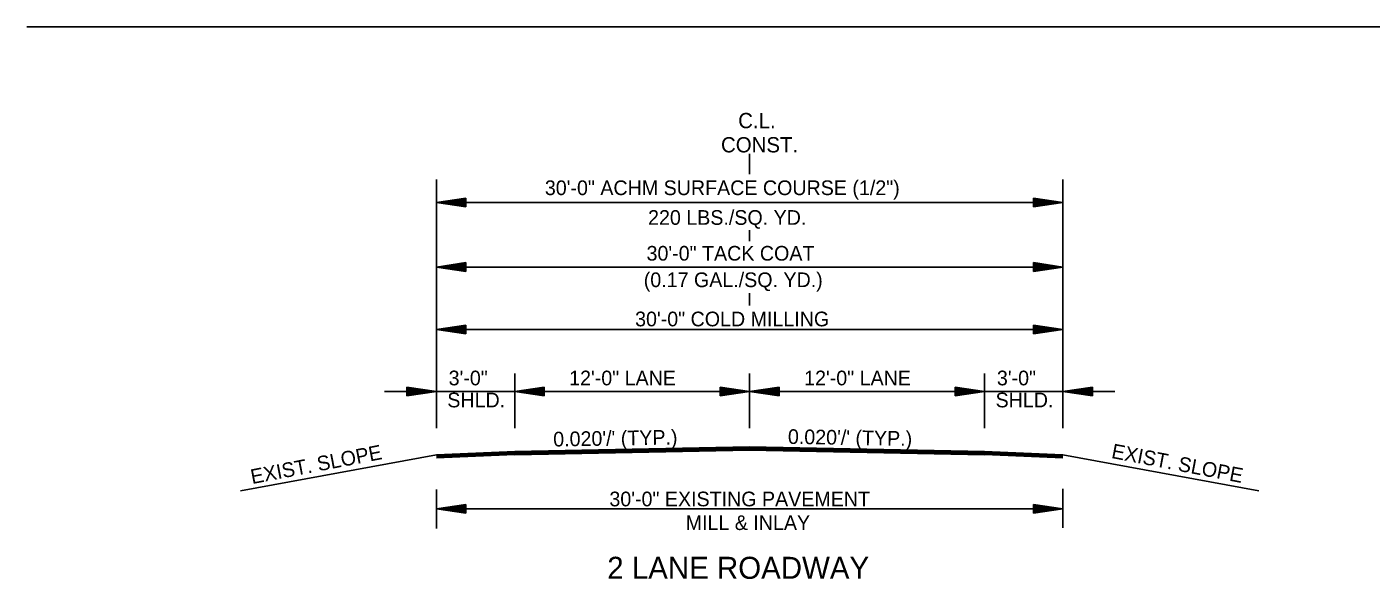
# Model space of a CAD drawing. Extents: x 549600 to 1930787, y -1955432 to 596640.
# Drawn here: x 550993 to 551679, y -1946446 to -1946164 of the extents above; entities that cross this region are included whole.
import ezdxf

# ---------------------------------------------------------------- set-up
doc = ezdxf.new("R2010")
doc.units = 0
doc.layers.add('R_Border', color=7, linetype='Continuous')
doc.layers.add('S_AREA_CALC', color=7, linetype='Continuous')

msp = doc.modelspace()

# ---------------------------------------------------------------- linework, layer by layer
at = {"layer": 'R_Border'}
msp.add_line((550992.91, -1946163.52), (552054.18, -1946163.52), dxfattribs=at)
at = {"layer": 'S_AREA_CALC'}
for p, q in [((551362.02, -1946238.76), (551362.02, -1946228.39)), ((551202.02, -1946368.61), (551202.02, -1946241.57)), ((551522.02, -1946368.61), (551522.02, -1946241.57)), ((551217.02, -1946251), (551202.02, -1946253.25)), ((551217.02, -1946251.37), (551204.52, -1946253.25)), ((551217.02, -1946251.75), (551207.1, -1946253.25)), ((551217.02, -1946252.13), (551209.6, -1946253.25)), ((551217.02, -1946255.5), (551217.02, -1946251)), ((551507.02, -1946251), (551522.02, -1946253.25)), ((551507.02, -1946251), (551507.02, -1946255.5)), ((551507.02, -1946251.37), (551519.51, -1946253.25)), ((551507.02, -1946251.75), (551516.93, -1946253.25)), ((551507.02, -1946252.13), (551514.44, -1946253.25)), ((551202.02, -1946253.25), (551522.02, -1946253.25)), ((551217.02, -1946255.5), (551202.02, -1946253.25)), ((551217.02, -1946255.12), (551204.52, -1946253.25)), ((551217.02, -1946254.74), (551207.1, -1946253.25)), ((551217.02, -1946254.36), (551209.6, -1946253.25)), ((551217.02, -1946252.51), (551212.14, -1946253.25)), ((551217.02, -1946253.97), (551212.14, -1946253.25)), ((551217.02, -1946252.89), (551214.65, -1946253.25)), ((551217.02, -1946253.6), (551214.65, -1946253.25)), ((551507.02, -1946252.52), (551511.89, -1946253.25)), ((551507.02, -1946252.89), (551509.39, -1946253.25)), ((551507.02, -1946255.5), (551522.02, -1946253.25)), ((551507.02, -1946253.98), (551511.89, -1946253.25)), ((551507.02, -1946254.74), (551516.93, -1946253.25)), ((551507.02, -1946255.12), (551519.51, -1946253.25)), ((551507.02, -1946254.36), (551514.44, -1946253.25)), ((551507.02, -1946253.6), (551509.39, -1946253.25)), ((551362.02, -1946272.99), (551362.02, -1946267.45)), ((551217.02, -1946283.96), (551202.02, -1946286.21)), ((551202.02, -1946286.21), (551522.02, -1946286.21)), ((551217.02, -1946288.46), (551202.02, -1946286.21)), ((551217.02, -1946284.34), (551204.52, -1946286.21)), ((551217.02, -1946288.09), (551204.52, -1946286.21)), ((551217.02, -1946284.72), (551207.1, -1946286.21)), ((551217.02, -1946287.7), (551207.1, -1946286.21)), ((551217.02, -1946285.09), (551209.6, -1946286.21)), ((551217.02, -1946287.33), (551209.6, -1946286.21)), ((551217.02, -1946285.48), (551212.14, -1946286.21)), ((551217.02, -1946286.94), (551212.14, -1946286.21)), ((551217.02, -1946285.86), (551214.65, -1946286.21)), ((551217.02, -1946286.56), (551214.65, -1946286.21)), ((551217.02, -1946288.46), (551217.02, -1946283.96)), ((551507.02, -1946283.96), (551522.02, -1946286.21)), ((551507.02, -1946283.96), (551507.02, -1946288.46)), ((551507.02, -1946284.34), (551519.51, -1946286.21)), ((551507.02, -1946284.72), (551516.93, -1946286.21)), ((551507.02, -1946285.09), (551514.44, -1946286.21)), ((551507.02, -1946285.48), (551511.89, -1946286.21)), ((551507.02, -1946285.86), (551509.39, -1946286.21)), ((551507.02, -1946288.46), (551522.02, -1946286.21)), ((551507.02, -1946286.95), (551511.89, -1946286.21)), ((551507.02, -1946287.7), (551516.93, -1946286.21)), ((551507.02, -1946288.09), (551519.51, -1946286.21)), ((551507.02, -1946287.33), (551514.44, -1946286.21)), ((551507.02, -1946286.56), (551509.39, -1946286.21)), ((551362.02, -1946305.95), (551362.02, -1946299.54)), ((551217.02, -1946315.94), (551202.02, -1946318.19)), ((551202.02, -1946318.19), (551522.02, -1946318.19)), ((551217.02, -1946320.44), (551202.02, -1946318.19)), ((551217.02, -1946316.31), (551204.52, -1946318.19)), ((551217.02, -1946320.06), (551204.52, -1946318.19)), ((551217.02, -1946316.69), (551207.1, -1946318.19)), ((551217.02, -1946319.68), (551207.1, -1946318.19)), ((551217.02, -1946317.07), (551209.6, -1946318.19)), ((551217.02, -1946319.3), (551209.6, -1946318.19)), ((551217.02, -1946317.45), (551212.14, -1946318.19)), ((551217.02, -1946318.91), (551212.14, -1946318.19)), ((551217.02, -1946317.83), (551214.65, -1946318.19)), ((551217.02, -1946318.54), (551214.65, -1946318.19)), ((551217.02, -1946320.44), (551217.02, -1946315.94)), ((551507.02, -1946315.94), (551522.02, -1946318.19)), ((551507.02, -1946315.94), (551507.02, -1946320.44)), ((551507.02, -1946316.31), (551519.51, -1946318.19)), ((551507.02, -1946316.69), (551516.93, -1946318.19)), ((551507.02, -1946317.07), (551514.44, -1946318.19)), ((551507.02, -1946317.46), (551511.89, -1946318.19)), ((551507.02, -1946317.83), (551509.39, -1946318.19)), ((551507.02, -1946320.44), (551522.02, -1946318.19)), ((551507.02, -1946318.92), (551511.89, -1946318.19)), ((551507.02, -1946319.68), (551516.93, -1946318.19)), ((551507.02, -1946320.06), (551519.51, -1946318.19)), ((551507.02, -1946319.3), (551514.44, -1946318.19)), ((551507.02, -1946318.54), (551509.39, -1946318.19)), ((551242.02, -1946368.61), (551242.02, -1946340.66)), ((551362.02, -1946368.61), (551362.02, -1946340.66)), ((551482.02, -1946368.61), (551482.02, -1946340.66)), ((551187.02, -1946347.59), (551202.02, -1946349.84)), ((551187.02, -1946347.59), (551187.02, -1946352.09)), ((551187.02, -1946347.97), (551199.51, -1946349.84)), ((551257.02, -1946347.59), (551242.02, -1946349.84)), ((551257.02, -1946347.97), (551244.52, -1946349.84)), ((551257.02, -1946347.59), (551257.02, -1946352.09)), ((551347.02, -1946347.59), (551362.02, -1946349.84)), ((551347.02, -1946347.59), (551347.02, -1946352.09)), ((551347.02, -1946347.97), (551359.51, -1946349.84)), ((551377.02, -1946347.59), (551362.02, -1946349.84)), ((551377.02, -1946347.97), (551364.52, -1946349.84)), ((551377.02, -1946347.59), (551377.02, -1946352.09)), ((551467.02, -1946347.59), (551482.02, -1946349.84)), ((551467.02, -1946347.59), (551467.02, -1946352.09)), ((551467.02, -1946347.97), (551479.51, -1946349.84)), ((551537.02, -1946347.59), (551522.02, -1946349.84)), ((551537.02, -1946347.97), (551524.52, -1946349.84)), ((551537.02, -1946347.59), (551537.02, -1946352.09)), ((551202.02, -1946349.84), (551175.5, -1946349.84)), ((551187.02, -1946348.35), (551196.93, -1946349.84)), ((551187.02, -1946348.73), (551194.44, -1946349.84)), ((551187.02, -1946349.12), (551191.89, -1946349.84)), ((551187.02, -1946349.49), (551189.39, -1946349.84)), ((551187.02, -1946352.09), (551202.02, -1946349.84)), ((551187.02, -1946350.58), (551191.89, -1946349.84)), ((551187.02, -1946351.34), (551196.93, -1946349.84)), ((551187.02, -1946351.72), (551199.51, -1946349.84)), ((551187.02, -1946350.96), (551194.44, -1946349.84)), ((551187.02, -1946350.2), (551189.39, -1946349.84)), ((551242.02, -1946349.84), (551202.02, -1946349.84)), ((551362.02, -1946349.84), (551242.02, -1946349.84)), ((551257.02, -1946352.09), (551242.02, -1946349.84)), ((551257.02, -1946351.72), (551244.52, -1946349.84)), ((551257.02, -1946348.35), (551247.1, -1946349.84)), ((551257.02, -1946351.34), (551247.1, -1946349.84)), ((551257.02, -1946348.73), (551249.6, -1946349.84)), ((551257.02, -1946350.96), (551249.6, -1946349.84)), ((551257.02, -1946349.12), (551252.14, -1946349.84)), ((551257.02, -1946350.58), (551252.14, -1946349.84)), ((551257.02, -1946349.49), (551254.65, -1946349.84)), ((551257.02, -1946350.2), (551254.65, -1946349.84)), ((551347.02, -1946348.35), (551356.93, -1946349.84)), ((551347.02, -1946348.73), (551354.44, -1946349.84)), ((551347.02, -1946349.12), (551351.89, -1946349.84)), ((551347.02, -1946349.49), (551349.39, -1946349.84)), ((551347.02, -1946352.09), (551362.02, -1946349.84)), ((551347.02, -1946350.58), (551351.89, -1946349.84)), ((551347.02, -1946351.34), (551356.93, -1946349.84)), ((551347.02, -1946351.72), (551359.51, -1946349.84)), ((551347.02, -1946350.96), (551354.44, -1946349.84)), ((551347.02, -1946350.2), (551349.39, -1946349.84)), ((551482.02, -1946349.84), (551362.02, -1946349.84)), ((551377.02, -1946352.09), (551362.02, -1946349.84)), ((551377.02, -1946351.72), (551364.52, -1946349.84)), ((551377.02, -1946348.35), (551367.1, -1946349.84)), ((551377.02, -1946351.34), (551367.1, -1946349.84)), ((551377.02, -1946348.73), (551369.6, -1946349.84)), ((551377.02, -1946350.96), (551369.6, -1946349.84)), ((551377.02, -1946349.12), (551372.14, -1946349.84)), ((551377.02, -1946350.58), (551372.14, -1946349.84)), ((551377.02, -1946349.49), (551374.65, -1946349.84)), ((551377.02, -1946350.2), (551374.65, -1946349.84)), ((551467.02, -1946348.35), (551476.93, -1946349.84)), ((551467.02, -1946348.73), (551474.44, -1946349.84)), ((551467.02, -1946349.12), (551471.89, -1946349.84)), ((551467.02, -1946349.49), (551469.39, -1946349.84)), ((551467.02, -1946352.09), (551482.02, -1946349.84)), ((551467.02, -1946350.58), (551471.89, -1946349.84)), ((551467.02, -1946351.34), (551476.93, -1946349.84)), ((551467.02, -1946351.72), (551479.51, -1946349.84)), ((551467.02, -1946350.96), (551474.44, -1946349.84)), ((551467.02, -1946350.2), (551469.39, -1946349.84)), ((551482.02, -1946349.84), (551522.02, -1946349.84)), ((551537.02, -1946352.09), (551522.02, -1946349.84)), ((551548.54, -1946349.84), (551522.02, -1946349.84)), ((551537.02, -1946351.72), (551524.52, -1946349.84)), ((551537.02, -1946348.35), (551527.1, -1946349.84)), ((551537.02, -1946351.34), (551527.1, -1946349.84)), ((551537.02, -1946348.73), (551529.6, -1946349.84)), ((551537.02, -1946350.96), (551529.6, -1946349.84)), ((551537.02, -1946349.12), (551532.14, -1946349.84)), ((551537.02, -1946350.58), (551532.14, -1946349.84)), ((551537.02, -1946349.49), (551534.65, -1946349.84)), ((551537.02, -1946350.2), (551534.65, -1946349.84)), ((551202.02, -1946382.15), (551101.95, -1946400.53)), ((551242.02, -1946380.55), (551202.02, -1946382.15)), ((551242.02, -1946380.85), (551202.02, -1946382.45)), ((551242.02, -1946381.15), (551202.02, -1946382.75)), ((551242.02, -1946381.45), (551202.02, -1946383.05)), ((551242.02, -1946381.75), (551202.02, -1946383.35)), ((551242.02, -1946382.05), (551202.02, -1946383.65)), ((551362.02, -1946378.15), (551242.02, -1946380.55)), ((551362.02, -1946378.45), (551242.02, -1946380.85)), ((551362.02, -1946378.75), (551242.02, -1946381.15)), ((551362.02, -1946379.05), (551242.02, -1946381.45)), ((551362.02, -1946379.35), (551242.02, -1946381.75)), ((551362.02, -1946379.65), (551242.02, -1946382.05)), ((551362.02, -1946379.82), (551242.02, -1946382.22)), ((551362.02, -1946378.15), (551482.02, -1946380.55)), ((551362.02, -1946378.45), (551482.02, -1946380.85)), ((551362.02, -1946378.75), (551482.02, -1946381.15)), ((551362.02, -1946379.05), (551482.02, -1946381.45)), ((551362.02, -1946379.35), (551482.02, -1946381.75)), ((551362.02, -1946379.65), (551482.02, -1946382.05)), ((551362.02, -1946379.82), (551482.02, -1946382.22)), ((551482.02, -1946380.55), (551522.02, -1946382.15)), ((551482.02, -1946380.85), (551522.02, -1946382.45)), ((551482.02, -1946381.15), (551522.02, -1946382.75)), ((551482.02, -1946381.45), (551522.02, -1946383.05)), ((551482.02, -1946381.75), (551522.02, -1946383.35)), ((551482.02, -1946382.05), (551522.02, -1946383.65)), ((551522.02, -1946382.15), (551622.09, -1946400.53)), ((551202.02, -1946399.81), (551202.02, -1946419.81)), ((551522.02, -1946399.56), (551522.02, -1946419.56)), ((551217.02, -1946407.56), (551202.02, -1946409.81)), ((551217.02, -1946412.06), (551202.02, -1946409.81)), ((551522.02, -1946409.81), (551202.02, -1946409.81)), ((551217.02, -1946407.94), (551204.52, -1946409.81)), ((551217.02, -1946411.69), (551204.52, -1946409.81)), ((551217.02, -1946408.32), (551207.1, -1946409.81)), ((551217.02, -1946411.31), (551207.1, -1946409.81)), ((551217.02, -1946408.7), (551209.6, -1946409.81)), ((551217.02, -1946410.93), (551209.6, -1946409.81)), ((551217.02, -1946409.09), (551212.14, -1946409.81)), ((551217.02, -1946410.55), (551212.14, -1946409.81)), ((551217.02, -1946409.46), (551214.65, -1946409.81)), ((551217.02, -1946410.17), (551214.65, -1946409.81)), ((551217.02, -1946407.56), (551217.02, -1946412.06)), ((551507.02, -1946407.56), (551522.02, -1946409.81)), ((551507.02, -1946412.06), (551507.02, -1946407.56)), ((551507.02, -1946407.94), (551519.51, -1946409.81)), ((551507.02, -1946408.32), (551516.93, -1946409.81)), ((551507.02, -1946408.7), (551514.44, -1946409.81)), ((551507.02, -1946409.08), (551511.89, -1946409.81)), ((551507.02, -1946409.46), (551509.39, -1946409.81)), ((551507.02, -1946412.06), (551522.02, -1946409.81)), ((551507.02, -1946410.54), (551511.89, -1946409.81)), ((551507.02, -1946411.31), (551516.93, -1946409.81)), ((551507.02, -1946411.69), (551519.51, -1946409.81)), ((551507.02, -1946410.93), (551514.44, -1946409.81)), ((551507.02, -1946410.17), (551509.39, -1946409.81))]:
    msp.add_line(p, q, dxfattribs=at)

# ---------------------------------------------------------------- texts
for s, height, p in [('C.L.', 7.8, (551356.17, -1946215.29)), ('CONST.', 7.8, (551347.39, -1946227.66)), ('30\'-0" ACHM SURFACE COURSE (1/2")', 7.5, (551257.43, -1946249.48)), ('220 LBS./SQ. YD. ', 7.5, (551310.14, -1946264.66)), ('30\'-0" TACK COAT', 7.5, (551309.37, -1946282.95)), ('(0.17 GAL./SQ. YD.)', 7.5, (551307.93, -1946296.49)), ('30\'-0" COLD MILLING ', 7.5, (551303.52, -1946316.52)), ('3\'-0"', 7.5, (551208.29, -1946346.67)), ('12\'-0" LANE', 7.5, (551269.84, -1946346.67)), ('12\'-0" LANE', 7.5, (551389.84, -1946346.67)), ('3\'-0"', 7.5, (551488.29, -1946346.67)), ('SHLD.', 7.5, (551207.61, -1946357.92)), ('SHLD.', 7.5, (551487.61, -1946357.92)), ('30\'-0" EXISTING PAVEMENT', 7.5, (551290.39, -1946408.49)), ('MILL & INLAY', 7.5, (551329.34, -1946420.59)), ('2 LANE ROADWAY', 11.25, (551289.29, -1946445.53))]:
    msp.add_text(s, height=height, dxfattribs=at).set_placement(p)
for s, rotation, p in [("0.020'/' (TYP.)", 0.97192, (551261.76, -1946377.95)), ("0.020'/' (TYP.)", 359.02808, (551381.5, -1946376.58)), ('EXIST. SLOPE', 10.88286, (551107.93, -1946397.15)), ('EXIST. SLOPE', 349.11714, (551546.4, -1946383.75))]:
    msp.add_text(s, height=7.5, rotation=rotation, dxfattribs=at).set_placement(p)

doc.saveas('drawing.dxf')
